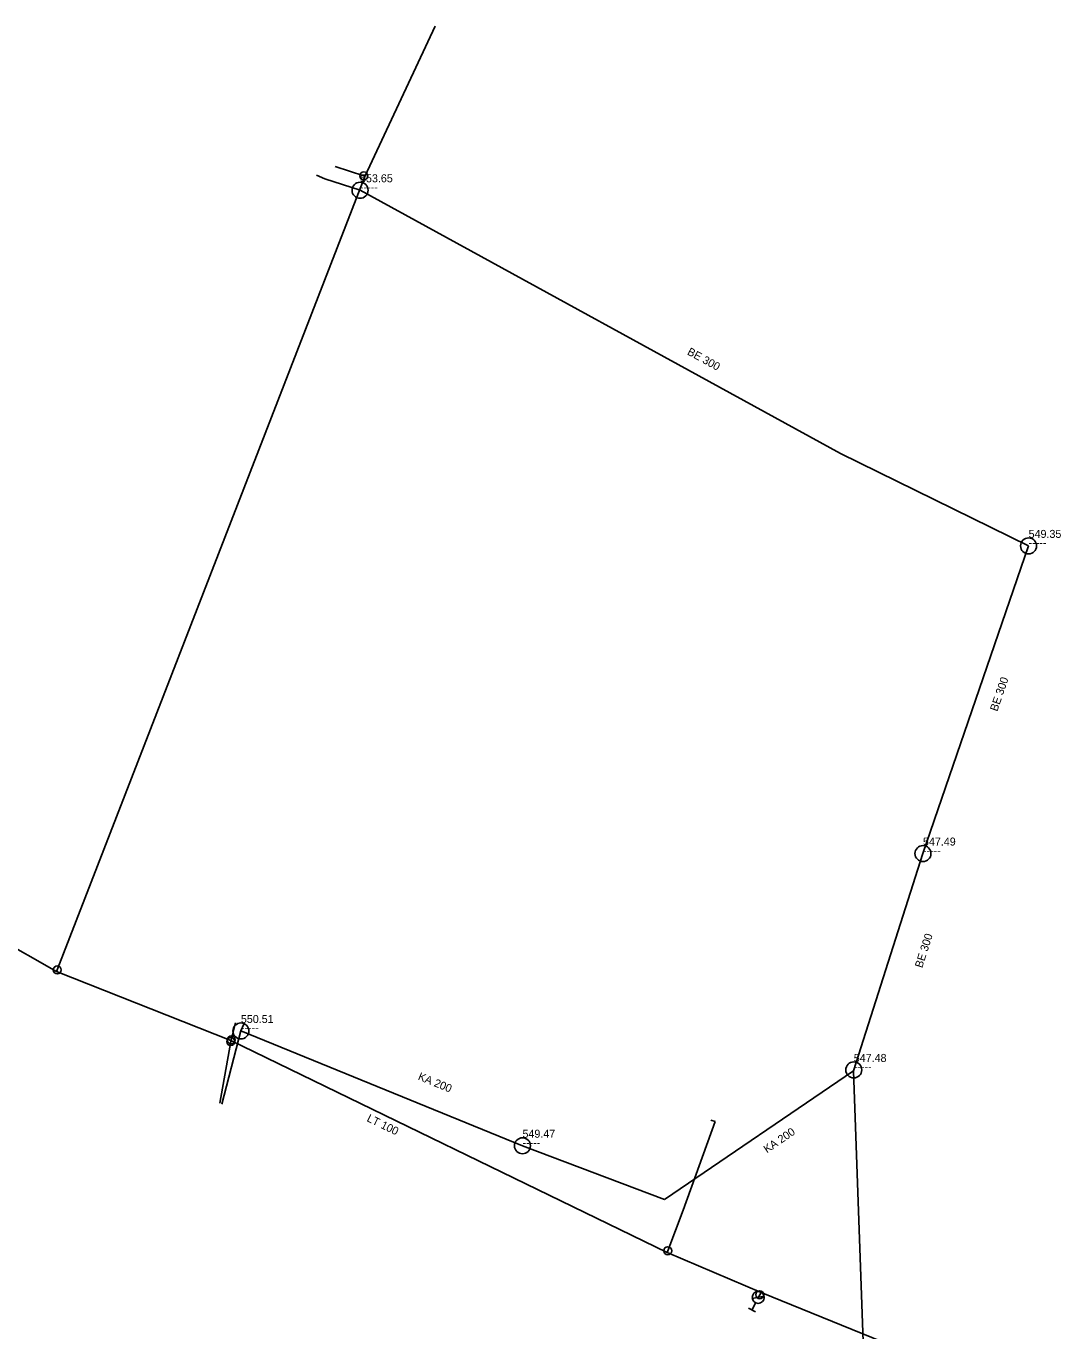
# Model space of a CAD drawing. Extents: x -701133 to -700495, y -1142806 to -1142020.
# Drawn here: x -700726.5 to -700597.2, y -1142269.2 to -1142106.2 of the extents above; entities that cross this region are included whole.
import ezdxf

# ---------------------------------------------------------------- set-up
doc = ezdxf.new("R2010")
doc.units = 0
doc.layers.add('Level 0', color=7, linetype='Continuous')

msp = doc.modelspace()

# ---------------------------------------------------------------- linework, layer by layer
at = {"layer": 'Level 0'}
for p, q in [((-700675.39, -1142106.15), (-700684.2, -1142124.95)), ((-700684.31, -1142124.88), (-700687.87, -1142123.71)), ((-700684.2, -1142124.95), (-700722.62, -1142224.1)), ((-700690.22, -1142124.78), (-700689.17, -1142125.23)), ((-700689.17, -1142125.23), (-700684.78, -1142126.67)), ((-700684.2, -1142124.95), (-700684.31, -1142124.88)), ((-700684.78, -1142126.67), (-700624.72, -1142159.56)), ((-700624.72, -1142159.56), (-700601.23, -1142171.11)), ((-700601.23, -1142171.11), (-700614.43, -1142209.56)), ((-700614.43, -1142209.56), (-700623.12, -1142236.71)), ((-700730.31, -1142219.96), (-700722.72, -1142224.3)), ((-700722.62, -1142224.1), (-700722.72, -1142224.3)), ((-700722.72, -1142224.3), (-700700.91, -1142232.94)), ((-700702.04, -1142240.87), (-700699.67, -1142231.73)), ((-700700.87, -1142232.85), (-700700.36, -1142230.7)), ((-700699.32, -1142230.88), (-700699.67, -1142231.73)), ((-700699.67, -1142231.73), (-700664.48, -1142246.07)), ((-700700.93, -1142233.06), (-700702.31, -1142240.76)), ((-700700.91, -1142232.94), (-700700.93, -1142233.06)), ((-700700.91, -1142232.94), (-700700.87, -1142232.85)), ((-700700.91, -1142232.94), (-700646.39, -1142259.41)), ((-700646.72, -1142252.8), (-700623.12, -1142236.71)), ((-700623.12, -1142236.71), (-700620.7, -1142305.05)), ((-700644.4, -1142254.14), (-700640.4, -1142243.06)), ((-700640.4, -1142243.06), (-700640.96, -1142242.88)), ((-700664.48, -1142246.07), (-700646.72, -1142252.8)), ((-700646.33, -1142259.2), (-700644.4, -1142254.14)), ((-700646.39, -1142259.41), (-700646.33, -1142259.2)), ((-700646.39, -1142259.41), (-700634.65, -1142264.41)), ((-700634.83, -1142264.69), (-700635.02, -1142265.02)), ((-700634.65, -1142264.41), (-700634.83, -1142264.69)), ((-700634.65, -1142264.41), (-700615.7, -1142272.11)), ((-700635.34, -1142266.81), (-700636.24, -1142266.37)), ((-700635.35, -1142265.69), (-700635.79, -1142266.59)), ((-700634.29, -1142264.86), (-700635.76, -1142265.18))]:
    msp.add_line(p, q, dxfattribs=at)
for centre, radius in [((-700684.31, -1142124.88), 0.5), ((-700684.78, -1142126.67), 1), ((-700601.23, -1142171.11), 1), ((-700614.43, -1142209.56), 1), ((-700722.62, -1142224.1), 0.5), ((-700699.67, -1142231.73), 1), ((-700700.93, -1142233.06), 0.5), ((-700700.87, -1142232.85), 0.5), ((-700623.08, -1142236.6), 1), ((-700664.48, -1142246.07), 1), ((-700646.33, -1142259.2), 0.5), ((-700635.02, -1142265.02), 0.75), ((-700634.83, -1142264.69), 0.5)]:
    msp.add_circle(centre, radius, dxfattribs=at)

# ---------------------------------------------------------------- texts
for s, p in [('553.65', (-700684.78, -1142125.67)), ('-----', (-700684.78, -1142126.77)), ('549.35', (-700601.23, -1142170.11)), ('-----', (-700601.23, -1142171.21)), ('547.49', (-700614.43, -1142208.56)), ('-----', (-700614.43, -1142209.66)), ('550.51', (-700699.67, -1142230.73)), ('-----', (-700699.67, -1142231.83)), ('547.48', (-700623.08, -1142235.6)), ('-----', (-700623.08, -1142236.7)), ('549.47', (-700664.48, -1142245.07)), ('-----', (-700664.48, -1142246.17))]:
    msp.add_text(s, height=1, dxfattribs=at).set_placement(p)
for s, rotation, p in [('BE 300', 331.294, (-700643.98, -1142147.14)), ('BE 300', 71.053, (-700605.15, -1142191.86)), ('BE 300', 72.261, (-700614.53, -1142223.92)), ('KA 200', 337.829, (-700677.62, -1142237.79)), ('LT 100', 334.103, (-700684.02, -1142242.97)), ('KA 200', 34.274, (-700633.93, -1142247.03))]:
    msp.add_text(s, height=1, rotation=rotation, dxfattribs=at).set_placement(p)

doc.saveas('drawing.dxf')
